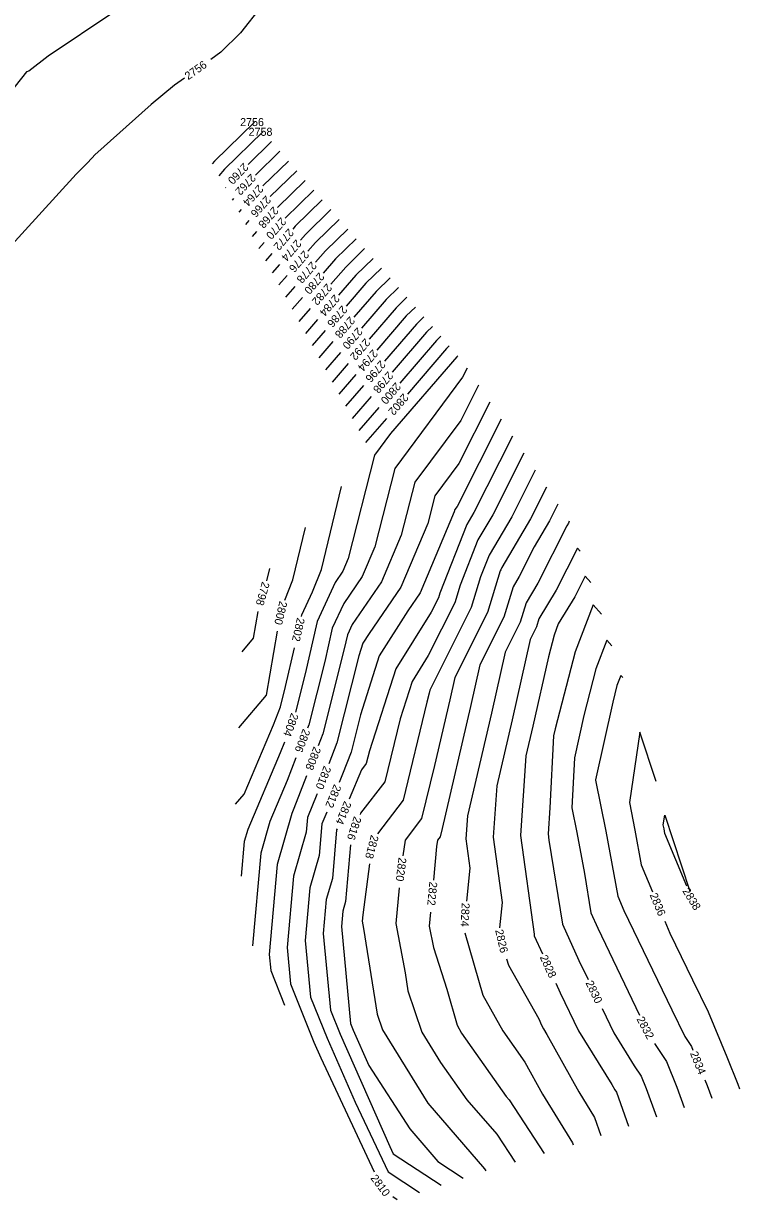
# Model space of a CAD drawing. Extents: x 1326424 to 1329294, y 1001359 to 1003823.
# Drawn here: x 1329115.4 to 1329294.3, y 1001606.6 to 1001900.5 of the extents above; entities that cross this region are included whole.
import ezdxf

# ---------------------------------------------------------------- set-up
doc = ezdxf.new("R2010")
doc.units = 0
doc.layers.add('Prop Rem of Exist Asph Pvmt', color=7, linetype='Continuous')
doc.layers.add('Scratch_Level_3', color=7, linetype='Continuous')

msp = doc.modelspace()

# ---------------------------------------------------------------- linework, layer by layer
at = {"layer": 'Prop Rem of Exist Asph Pvmt'}
for points in [[(1329177.34, 1001871.02), (1329171.49, 1001865.32)], [(1329165.98, 1001859.53), (1329165.87, 1001859.41)], [(1329198.51, 1001846.69), (1329193.39, 1001841.69), (1329190.3, 1001838.11)], [(1329185.08, 1001832.04), (1329182.55, 1001829.1)], [(1329219.69, 1001822.36), (1329218.61, 1001821.31), (1329209.41, 1001810.61)], [(1329204.19, 1001804.55), (1329199.22, 1001798.78)], [(1329246.12, 1001784.62), (1329242.11, 1001776.7), (1329234.95, 1001764.51), (1329234.67, 1001763.94), (1329234.55, 1001763.75), (1329231.31, 1001753.32), (1329223.19, 1001737.07), (1329221.93, 1001731.47), (1329218.11, 1001715.09), (1329214.89, 1001701.82), (1329210.76, 1001696.43), (1329210.22, 1001692.44)], [(1329180.68, 1001756.38), (1329182.71, 1001761.44), (1329185.88, 1001774.54)], [(1329169.19, 1001724.45), (1329176.08, 1001732.6), (1329178.87, 1001748.63)], [(1329209.24, 1001684.5), (1329208.41, 1001675.53), (1329210.74, 1001663.27), (1329211.47, 1001658.75), (1329214.94, 1001648.41), (1329219.63, 1001640.78), (1329226.22, 1001631.48), (1329233.65, 1001622.89), (1329238.23, 1001615.9)]]:
    msp.add_lwpolyline(points, dxfattribs=at)
at = {"layer": 'Scratch_Level_3'}
for points in [[(1329218.96, 1001957.62), (1329218.73, 1001955.36), (1329214.54, 1001962.68), (1329214.58, 1001959.61), (1329210.14, 1001953.43), (1329205.86, 1001946.25), (1329202, 1001940.69), (1329193.38, 1001928.7), (1329189.62, 1001924.14), (1329184.21, 1001917.08), (1329174.87, 1001904.87), (1329169.64, 1001898.23), (1329164.73, 1001893.32), (1329162.17, 1001891.51)], [(1329137.98, 1001903.38), (1329121.57, 1001892.33), (1329116.71, 1001888.64), (1329116.15, 1001888.47), (1329101.59, 1001870.1), (1329101.18, 1001869.26), (1329099.55, 1001867.32), (1329098.09, 1001863.58), (1329097.35, 1001868.56), (1329096.72, 1001871.54), (1329105.93, 1001886.52), (1329099.92, 1001902.1), (1329100.02, 1001902.32)], [(1329155.63, 1001886.9), (1329153.15, 1001885.15), (1329147.26, 1001880.26), (1329133.24, 1001867.66), (1329132.51, 1001866.94), (1329131.21, 1001865.52), (1329128.52, 1001862.83), (1329110.71, 1001843.27), (1329110.13, 1001842.68), (1329109.31, 1001841.84), (1329103.66, 1001835.14), (1329098.86, 1001830.25), (1329097.92, 1001829.32), (1329096.87, 1001828.12), (1329081.61, 1001821.3)], [(1329173.11, 1001875.88), (1329163.11, 1001866.15), (1329162.53, 1001865.47)], [(1329175.22, 1001873.45), (1329165.64, 1001864.11), (1329164.2, 1001862.44)], [(1329179.46, 1001868.58), (1329173.34, 1001862.63)], [(1329181.58, 1001866.15), (1329175.19, 1001859.93)], [(1329183.69, 1001863.72), (1329177.04, 1001857.24)], [(1329185.81, 1001861.29), (1329178.9, 1001854.55)], [(1329187.93, 1001858.85), (1329180.77, 1001851.88), (1329180.75, 1001851.85)], [(1329167.89, 1001856.79), (1329167.54, 1001856.38)], [(1329190.04, 1001856.42), (1329183.29, 1001849.84), (1329182.66, 1001849.1)], [(1329169.8, 1001854.04), (1329169.2, 1001853.35)], [(1329192.16, 1001853.99), (1329185.82, 1001847.8), (1329184.57, 1001846.35)], [(1329194.28, 1001851.55), (1329188.34, 1001845.77), (1329186.48, 1001843.6)], [(1329171.71, 1001851.29), (1329170.87, 1001850.31)], [(1329173.62, 1001848.54), (1329172.54, 1001847.28)], [(1329196.4, 1001849.12), (1329190.86, 1001843.73), (1329188.39, 1001840.86)], [(1329175.53, 1001845.79), (1329174.21, 1001844.25)], [(1329177.44, 1001843.04), (1329175.87, 1001841.22)], [(1329200.63, 1001844.25), (1329195.91, 1001839.65), (1329192.21, 1001835.36)], [(1329179.35, 1001840.29), (1329177.54, 1001838.19)], [(1329202.75, 1001841.82), (1329198.43, 1001837.61), (1329194.12, 1001832.61)], [(1329181.26, 1001837.54), (1329179.21, 1001835.16)], [(1329204.87, 1001839.39), (1329200.95, 1001835.58), (1329196.03, 1001829.86)], [(1329206.98, 1001836.95), (1329203.48, 1001833.54), (1329197.94, 1001827.11)], [(1329183.17, 1001834.79), (1329180.88, 1001832.13)], [(1329209.1, 1001834.52), (1329206, 1001831.5), (1329199.85, 1001824.36)], [(1329211.22, 1001832.09), (1329208.52, 1001829.46), (1329201.76, 1001821.61)], [(1329186.99, 1001829.29), (1329184.21, 1001826.06)], [(1329213.33, 1001829.66), (1329211.05, 1001827.42), (1329203.68, 1001818.86)], [(1329188.9, 1001826.54), (1329185.88, 1001823.03)], [(1329215.45, 1001827.22), (1329213.57, 1001825.39), (1329205.59, 1001816.11)], [(1329190.81, 1001823.8), (1329187.55, 1001820)], [(1329217.57, 1001824.79), (1329216.09, 1001823.35), (1329207.5, 1001813.36)], [(1329192.72, 1001821.05), (1329189.22, 1001816.97)], [(1329221.8, 1001819.92), (1329221.14, 1001819.27), (1329211.32, 1001807.86)], [(1329223.92, 1001817.49), (1329223.66, 1001817.24), (1329207.1, 1001798), (1329203.13, 1001792.66), (1329196.56, 1001766.83), (1329195.22, 1001763.66), (1329193.24, 1001760.78), (1329188.74, 1001751.06), (1329185.77, 1001737.96), (1329183.36, 1001728.39)], [(1329194.64, 1001818.3), (1329190.88, 1001813.94)], [(1329226.29, 1001814.41), (1329225.12, 1001812.09), (1329208.15, 1001789.26), (1329203.18, 1001769.73), (1329200.05, 1001762.3), (1329195.4, 1001755.54), (1329192.54, 1001749.38), (1329190.66, 1001741.08), (1329186.66, 1001725.21), (1329186.35, 1001724.4)], [(1329196.55, 1001815.55), (1329192.55, 1001810.91)], [(1329198.46, 1001812.8), (1329194.22, 1001807.88)], [(1329229.13, 1001810.15), (1329224.66, 1001801.33), (1329213.16, 1001785.87), (1329209.8, 1001772.64), (1329204.87, 1001760.94), (1329197.55, 1001750.29), (1329196.35, 1001747.7), (1329195.56, 1001744.2), (1329190.19, 1001722.94), (1329189.03, 1001719.95)], [(1329200.37, 1001810.05), (1329195.89, 1001804.84)], [(1329202.28, 1001807.3), (1329197.56, 1001801.81)], [(1329231.96, 1001805.9), (1329224.2, 1001790.57), (1329218.18, 1001782.47), (1329216.42, 1001775.54), (1329209.69, 1001759.59), (1329201.75, 1001748.03), (1329200.23, 1001745.61), (1329199.22, 1001742.48), (1329193.72, 1001720.68), (1329191.69, 1001715.45)], [(1329234.79, 1001801.64), (1329223.74, 1001779.81), (1329223.2, 1001779.08), (1329223.04, 1001778.45), (1329214.51, 1001758.23), (1329211.44, 1001753.75), (1329204.31, 1001742.43), (1329199.61, 1001727.76), (1329197.26, 1001718.42), (1329195.11, 1001712.9), (1329194.25, 1001710.81)], [(1329206.1, 1001801.8), (1329200.89, 1001795.75)], [(1329237.62, 1001797.39), (1329227.95, 1001778.27), (1329226.19, 1001775.28), (1329219.44, 1001758.12), (1329219.07, 1001756.93), (1329217.29, 1001753.38), (1329208.4, 1001739.24), (1329201.82, 1001718.73), (1329201.06, 1001715.58), (1329199.85, 1001714), (1329196.8, 1001706.63)], [(1329240.46, 1001793.13), (1329232.67, 1001777.74), (1329228.97, 1001771.44), (1329224.52, 1001760.16), (1329223.15, 1001755.72), (1329216.54, 1001742.51), (1329212.48, 1001736.06), (1329209.48, 1001726.7), (1329205.67, 1001710.99), (1329199.64, 1001703.12), (1329199.5, 1001702.78)], [(1329243.29, 1001788.88), (1329237.39, 1001777.22), (1329231.74, 1001767.6), (1329229.61, 1001762.21), (1329227.23, 1001754.52), (1329216.92, 1001733.9), (1329216.74, 1001733.12), (1329216.21, 1001730.85), (1329210.28, 1001706.41), (1329203.84, 1001697.99)], [(1329184.84, 1001752.31), (1329184.94, 1001752.74), (1329187.6, 1001758.5), (1329189.82, 1001764.01), (1329194.85, 1001784.76)], [(1329248.96, 1001780.37), (1329246.84, 1001776.18), (1329243.05, 1001769.73), (1329239.29, 1001762.27), (1329237.76, 1001759.74), (1329235.39, 1001752.12), (1329229.46, 1001740.25), (1329227.12, 1001729.82), (1329220.01, 1001699.34), (1329219.5, 1001697.24), (1329218.85, 1001696.38), (1329218.63, 1001694.78), (1329217.86, 1001686.39)], [(1329251.79, 1001776.11), (1329251.56, 1001775.65), (1329251.14, 1001774.95), (1329243.92, 1001760.59), (1329240.97, 1001755.73), (1329239.48, 1001750.92), (1329235.73, 1001743.42), (1329232.31, 1001728.17), (1329226.32, 1001702.47), (1329225.93, 1001696.71), (1329226.92, 1001689.41), (1329226.12, 1001681.11)], [(1329254.47, 1001768.66), (1329253.82, 1001769.4), (1329248.55, 1001758.92), (1329244.18, 1001751.72), (1329243.56, 1001749.72), (1329242, 1001746.59), (1329237.5, 1001726.51), (1329233.64, 1001709.97), (1329232.78, 1001697.13), (1329234.99, 1001680.84), (1329234.37, 1001674.47)], [(1329176.17, 1001761.21), (1329176.92, 1001764.32)], [(1329257.14, 1001760.76), (1329255.74, 1001762.34), (1329253.17, 1001757.24), (1329249.04, 1001750.43), (1329247.97, 1001747.66), (1329246.58, 1001742.23), (1329242.69, 1001724.86), (1329240.96, 1001717.48), (1329239.62, 1001697.54), (1329242.97, 1001672.91), (1329243.03, 1001672.49), (1329245.11, 1001667.95)], [(1329259.8, 1001752.86), (1329257.74, 1001755.19), (1329253.22, 1001743.45), (1329248.26, 1001724.18), (1329247.88, 1001722.46), (1329246.91, 1001704.48), (1329246.47, 1001697.96), (1329246.68, 1001696.43), (1329250.09, 1001675.36), (1329254.21, 1001666.35), (1329256.51, 1001661.56)], [(1329169.99, 1001743.5), (1329172.85, 1001746.88), (1329174.01, 1001753.54)], [(1329262.46, 1001744.96), (1329261.21, 1001746.37), (1329258.46, 1001739.24), (1329255.45, 1001727.53), (1329253.11, 1001716.95), (1329252.44, 1001704.49), (1329253.7, 1001698.28), (1329255.56, 1001688.07), (1329257.15, 1001678.23), (1329258.89, 1001674.43), (1329269.35, 1001652.61)], [(1329168.4, 1001705.41), (1329170.5, 1001707.89), (1329177.85, 1001725.24), (1329179.59, 1001729.73), (1329180.88, 1001734.84), (1329183.07, 1001744.5)], [(1329265.13, 1001737.06), (1329264.68, 1001737.56), (1329263.71, 1001735.03), (1329262.64, 1001730.89), (1329258.35, 1001711.51), (1329258.34, 1001711.43), (1329260.96, 1001698.61), (1329263.9, 1001682.43), (1329265.41, 1001678.8), (1329277.39, 1001653.99), (1329280.68, 1001647.29), (1329282.34, 1001644.79), (1329282.69, 1001643.92)], [(1329273.49, 1001711.04), (1329269.4, 1001723.36), (1329266.81, 1001705.82), (1329268.21, 1001698.93), (1329269.79, 1001690.25), (1329272.59, 1001683.51)], [(1329180.57, 1001720.9), (1329179.55, 1001718.26), (1329171.41, 1001699.04), (1329170.56, 1001696.08), (1329169.79, 1001687.38)], [(1329183.45, 1001716.94), (1329181.25, 1001711.28), (1329176.92, 1001701.06), (1329174.66, 1001693.18), (1329172.61, 1001670.02)], [(1329186.13, 1001712.5), (1329182.94, 1001704.29), (1329182.43, 1001703.08), (1329178.76, 1001690.28), (1329176.77, 1001667.84), (1329177.16, 1001663.82), (1329180.58, 1001655.19)], [(1329188.79, 1001707.99), (1329188.71, 1001707.78), (1329186.33, 1001702.02), (1329186.01, 1001698.36), (1329182.86, 1001687.38), (1329181.29, 1001669.59), (1329182.15, 1001660.51), (1329187.97, 1001645.86), (1329189.67, 1001642), (1329203.06, 1001613.51)], [(1329191.19, 1001703.42), (1329189.98, 1001700.49), (1329189.29, 1001692.58), (1329186.96, 1001684.47), (1329185.8, 1001671.34), (1329187.15, 1001657.19), (1329191.24, 1001646.88), (1329198.3, 1001630.93), (1329206.49, 1001613.49), (1329214.31, 1001608.36)], [(1329275.47, 1001699.25), (1329275.27, 1001700.2), (1329275.63, 1001702.62), (1329281.94, 1001683.61)], [(1329193.75, 1001699.24), (1329193.63, 1001698.96), (1329192.57, 1001686.81), (1329191.06, 1001681.57), (1329190.31, 1001673.09), (1329192.14, 1001653.88), (1329194.52, 1001647.9), (1329206.93, 1001619.85), (1329207.79, 1001618.03), (1329219.8, 1001610.14)], [(1329281.14, 1001684.92), (1329275.68, 1001698.06), (1329275.47, 1001699.25)], [(1329197.09, 1001695.22), (1329195.84, 1001681.04), (1329195.16, 1001678.67), (1329194.82, 1001674.83), (1329197.14, 1001650.57), (1329197.79, 1001648.93), (1329201.69, 1001640.11), (1329211.91, 1001624.22), (1329218.92, 1001616.1), (1329225.29, 1001611.92)], [(1329201.86, 1001690.44), (1329200.16, 1001677.77), (1329200.02, 1001676.17), (1329200.36, 1001674.34), (1329203.8, 1001652.94), (1329205.13, 1001648.97), (1329216.41, 1001630.63), (1329216.41, 1001630.62), (1329230.57, 1001614.27), (1329230.93, 1001613.73)], [(1329217.12, 1001678.42), (1329216.8, 1001674.9), (1329217.81, 1001669.57), (1329221.19, 1001659.13), (1329223.77, 1001650.16), (1329224.89, 1001648.18), (1329233, 1001636.6), (1329236.02, 1001632.33), (1329236.73, 1001631.51), (1329245.52, 1001618.07)], [(1329275.66, 1001676.12), (1329276.89, 1001673.16), (1329282.55, 1001661.44), (1329286.47, 1001653.45), (1329291.14, 1001642.26), (1329293.93, 1001635.37), (1329294.32, 1001634.27)], [(1329225.72, 1001673.19), (1329230.19, 1001657.64), (1329235.19, 1001648.76), (1329240.7, 1001640.89), (1329245.13, 1001632.9), (1329252.59, 1001620.77), (1329252.77, 1001620.27)], [(1329236.13, 1001666.74), (1329236.6, 1001665.11), (1329244.17, 1001651.7), (1329244.85, 1001650.19), (1329245.32, 1001649.21), (1329246.18, 1001647.83), (1329254.16, 1001633.45), (1329258.07, 1001627.09), (1329259.7, 1001622.6)], [(1329248.44, 1001660.67), (1329249.53, 1001658.27), (1329254.12, 1001648.71), (1329262.45, 1001635.32), (1329263.19, 1001633.99), (1329263.55, 1001633.4), (1329266.62, 1001624.93)], [(1329259.97, 1001654.35), (1329262.91, 1001648.2), (1329268.01, 1001640.01), (1329269.75, 1001637.38), (1329270.98, 1001634.35), (1329273.55, 1001627.27)], [(1329273.09, 1001645.55), (1329276.05, 1001641.08), (1329278.63, 1001634.69), (1329280.47, 1001629.6)], [(1329285.68, 1001636.5), (1329286.28, 1001635.03), (1329287.4, 1001631.94)], [(1329207.68, 1001607.32), (1329208.81, 1001606.58)]]:
    msp.add_lwpolyline(points, dxfattribs=at)

# ---------------------------------------------------------------- texts
at = {"layer": 'Prop Rem of Exist Asph Pvmt'}
for s, rotation, p in [('2760', 226.3572, (1329170.37, 1001865.8)), ('2780', 229.2815, (1329189.27, 1001838.44)), ('2800', 229.2815, (1329208.38, 1001810.95)), ('2800', 256.8387, (1329179.39, 1001756.28)), ('2820', 262.8938, (1329209.14, 1001692.15))]:
    msp.add_text(s, height=2, rotation=rotation, dxfattribs=at).set_placement(p)
at = {"layer": 'Scratch_Level_3'}
for s, rotation, p in [('2756', 35.1965, (1329156.55, 1001886.32)), ('2762', 226.947, (1329172.2, 1001863.11)), ('2764', 227.5368, (1329174.08, 1001860.37)), ('2766', 228.1264, (1329175.95, 1001857.64)), ('2768', 228.7157, (1329177.83, 1001854.91)), ('2770', 229.2815, (1329179.72, 1001852.19)), ('2772', 229.2815, (1329181.63, 1001849.44)), ('2774', 229.2815, (1329183.54, 1001846.69)), ('2776', 229.2815, (1329185.45, 1001843.94)), ('2778', 229.2815, (1329187.36, 1001841.19)), ('2782', 229.2815, (1329191.18, 1001835.69)), ('2784', 229.2815, (1329193.09, 1001832.94)), ('2786', 229.2815, (1329195, 1001830.19)), ('2788', 229.2815, (1329196.91, 1001827.45)), ('2790', 229.2815, (1329198.82, 1001824.7)), ('2792', 229.2815, (1329200.73, 1001821.95)), ('2794', 229.2815, (1329202.65, 1001819.2)), ('2796', 229.2815, (1329204.56, 1001816.45)), ('2798', 229.2815, (1329206.47, 1001813.7)), ('2802', 229.2815, (1329210.29, 1001808.2)), ('2798', 254.2338, (1329175.02, 1001761.11)), ('2802', 257.2429, (1329183.77, 1001752.12)), ('2804', 249.6102, (1329182.33, 1001728.33)), ('2806', 248.7698, (1329185.26, 1001724.37)), ('2808', 248.7698, (1329187.94, 1001719.93)), ('2810', 248.7698, (1329190.49, 1001715.11)), ('2812', 247.5529, (1329193.04, 1001710.5)), ('2814', 247.5529, (1329195.59, 1001706.32)), ('2816', 252.3319, (1329198, 1001702.48)), ('2818', 255.3446, (1329202.25, 1001697.81)), ('2822', 264.7243, (1329216.83, 1001686.07)), ('2838', 301.4089, (1329279.97, 1001683.73)), ('2836', 292.5505, (1329271.84, 1001682.71)), ('2824', 267.0917, (1329224.92, 1001680.76)), ('2826', 282.8532, (1329233.26, 1001673.85)), ('2828', 294.5616, (1329244.37, 1001667.15)), ('2830', 295.6166, (1329255.8, 1001660.72)), ('2832', 297.882, (1329268.54, 1001651.68)), ('2834', 291.968, (1329281.93, 1001643.13)), ('2810', 306.7843, (1329202.01, 1001611.89))]:
    msp.add_text(s, height=2, rotation=rotation, dxfattribs=at).set_placement(p)
for s, p in [('2756', (1329169.52, 1001874.88)), ('2758', (1329171.64, 1001872.45))]:
    msp.add_text(s, height=2, dxfattribs=at).set_placement(p)

doc.saveas('drawing.dxf')
